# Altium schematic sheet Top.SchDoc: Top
size A4; Date: Not used; ApprovedBy: Not used; CheckedBy: Not used; Author: Not used; CompanyName: STMicroelectronics; DrawnBy: Not used; Engineer: Not used; Organization: Not used; Address1: Not used; Address2: Not used; Address3: Not used; Address4: Not used; DocumentNumber: Not used; Revision: Not used; SheetNumber: 2; SheetTotal: 12
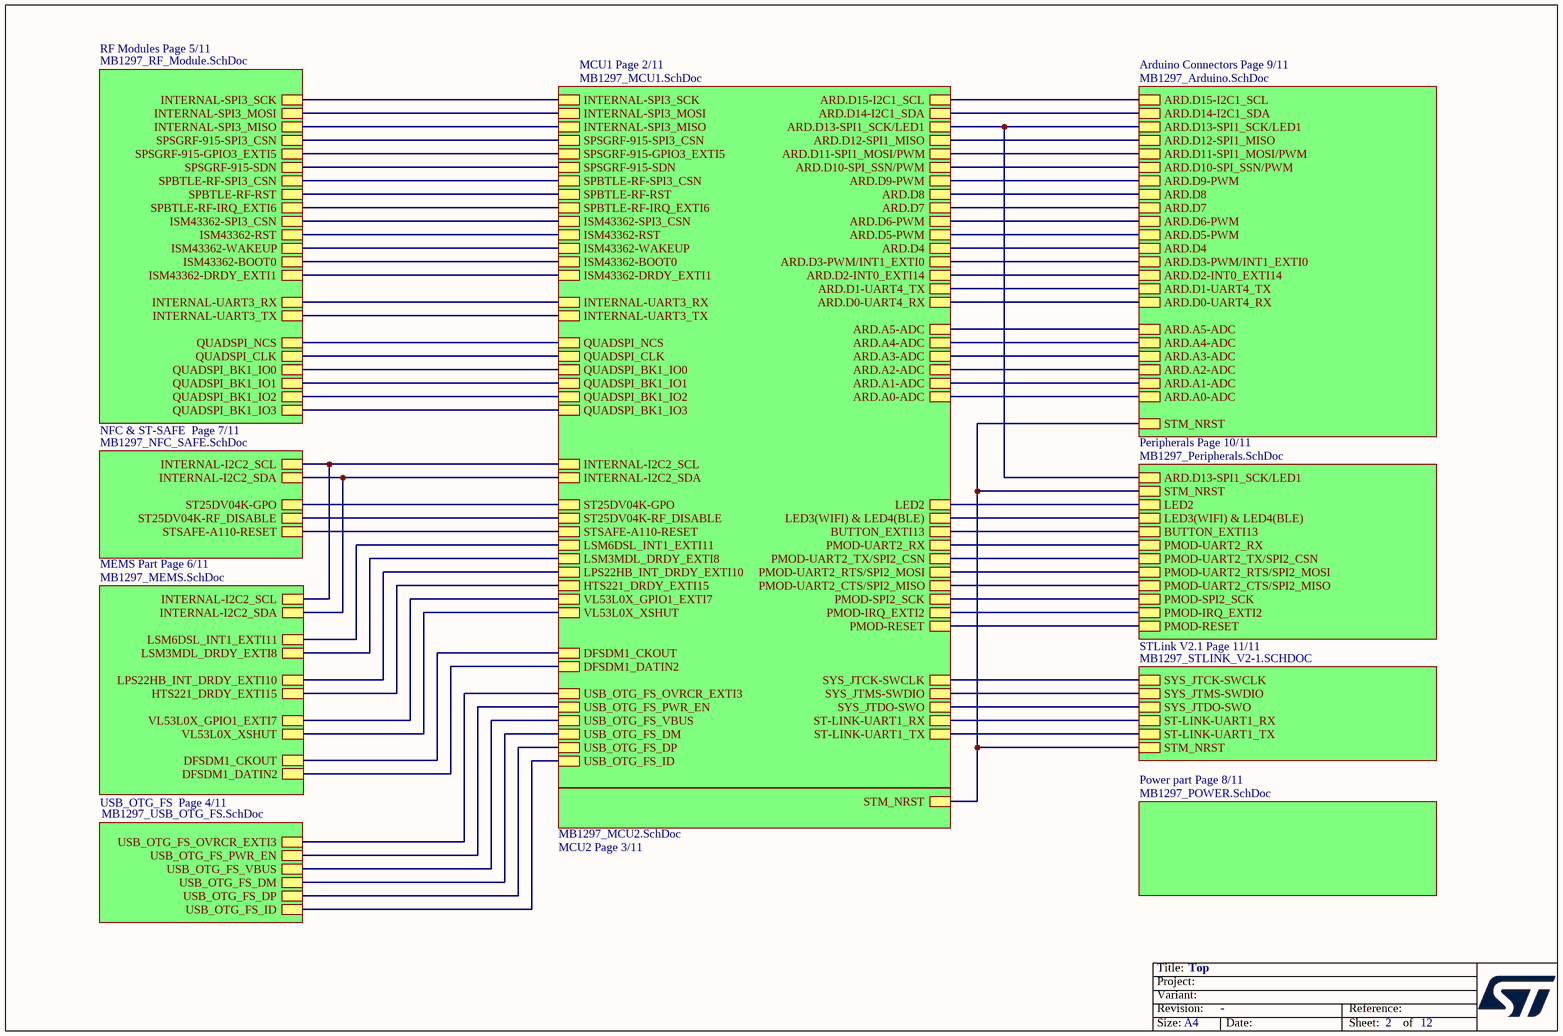
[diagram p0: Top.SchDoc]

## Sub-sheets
Arduino Connectors Page 9/11 = MB1297_Arduino.SchDoc: ARD.D3-PWM/INT1_EXTI0, ARD.D2-INT0_EXTI14, ARD.D1-UART4_TX, ARD.D0-UART4_RX, ARD.A5-ADC, ARD.A4-ADC, ARD.A3-ADC, ARD.A2-ADC, ARD.A1-ADC, ARD.A0-ADC, ARD.D4, ARD.D5-PWM, ARD.D6-PWM, ARD.D7, ARD.D8, ARD.D9-PWM, ARD.D10-SPI_SSN/PWM, ARD.D11-SPI1_MOSI/PWM, ARD.D12-SPI1_MISO, ARD.D13-SPI1_SCK/LED1, ARD.D14-I2C1_SDA, ARD.D15-I2C1_SCL, STM_NRST
MCU1 Page 2/11 = MB1297_MCU1.SchDoc: INTERNAL-SPI3_SCK, INTERNAL-SPI3_MOSI, INTERNAL-SPI3_MISO, ISM43362-SPI3_CSN, SPSGRF-915-SDN, SPSGRF-915-SPI3_CSN, SPBTLE-RF-SPI3_CSN, SYS_JTCK-SWCLK, SYS_JTMS-SWDIO, ARD.D3-PWM/INT1_EXTI0, ARD.D2-INT0_EXTI14, ARD.D1-UART4_TX, ARD.D0-UART4_RX, ARD.D4, ARD.D5-PWM, ARD.D6-PWM, ARD.D7, ARD.D8, ARD.D9-PWM, ARD.D10-SPI_SSN/PWM, ARD.D11-SPI1_MOSI/PWM, ARD.D12-SPI1_MISO, ARD.D13-SPI1_SCK/LED1, ARD.D14-I2C1_SDA, ARD.D15-I2C1_SCL, ARD.A5-ADC, ARD.A4-ADC, ARD.A3-ADC, ARD.A2-ADC, ARD.A1-ADC, ARD.A0-ADC, USB_OTG_FS_OVRCR_EXTI3, USB_OTG_FS_PWR_EN, USB_OTG_FS_VBUS, USB_OTG_FS_DM, USB_OTG_FS_DP, USB_OTG_FS_ID, INTERNAL-I2C2_SCL, INTERNAL-I2C2_SDA, ST25DV04K-GPO, ST25DV04K-RF_DISABLE, STSAFE-A110-RESET, LED2, LED3(WIFI) & LED4(BLE), BUTTON_EXTI13, PMOD-UART2_RTS/SPI2_MOSI, PMOD-UART2_CTS/SPI2_MISO, PMOD-SPI2_SCK, PMOD-IRQ_EXTI2, PMOD-RESET, PMOD-UART2_RX, PMOD-UART2_TX/SPI2_CSN, LSM6DSL_INT1_EXTI11, LSM3MDL_DRDY_EXTI8, LPS22HB_INT_DRDY_EXTI10, HTS221_DRDY_EXTI15, VL53L0X_GPIO1_EXTI7, VL53L0X_XSHUT, DFSDM1_CKOUT, DFSDM1_DATIN2, SPBTLE-RF-RST, SYS_JTDO-SWO, QUADSPI_NCS, QUADSPI_CLK, QUADSPI_BK1_IO0, QUADSPI_BK1_IO1, QUADSPI_BK1_IO2, QUADSPI_BK1_IO3, SPSGRF-915-GPIO3_EXTI5, SPBTLE-RF-IRQ_EXTI6, ISM43362-DRDY_EXTI1, ISM43362-RST, ISM43362-WAKEUP, ISM43362-BOOT0, INTERNAL-UART3_RX, INTERNAL-UART3_TX, ST-LINK-UART1_RX, ST-LINK-UART1_TX
MCU2 Page 3/11 = MB1297_MCU2.SchDoc: STM_NRST
MEMS Part Page 6/11 = MB1297_MEMS.SchDoc: INTERNAL-I2C2_SCL, INTERNAL-I2C2_SDA, LSM6DSL_INT1_EXTI11, LSM3MDL_DRDY_EXTI8, LPS22HB_INT_DRDY_EXTI10, HTS221_DRDY_EXTI15, VL53L0X_GPIO1_EXTI7, VL53L0X_XSHUT, DFSDM1_CKOUT, DFSDM1_DATIN2
NFC & ST-SAFE  Page 7/11 = MB1297_NFC_SAFE.SchDoc: INTERNAL-I2C2_SCL, INTERNAL-I2C2_SDA, ST25DV04K-GPO, ST25DV04K-RF_DISABLE, STSAFE-A110-RESET
Peripherals Page 10/11 = MB1297_Peripherals.SchDoc: STM_NRST, ARD.D13-SPI1_SCK/LED1, LED2, LED3(WIFI) & LED4(BLE), BUTTON_EXTI13, PMOD-UART2_RTS/SPI2_MOSI, PMOD-UART2_CTS/SPI2_MISO, PMOD-SPI2_SCK, PMOD-IRQ_EXTI2, PMOD-RESET, PMOD-UART2_RX, PMOD-UART2_TX/SPI2_CSN
Power part Page 8/11 = MB1297_POWER.SchDoc: no entries
RF Modules Page 5/11 = MB1297_RF_Module.SchDoc: INTERNAL-SPI3_SCK, INTERNAL-SPI3_MOSI, INTERNAL-SPI3_MISO, SPSGRF-915-SPI3_CSN, SPSGRF-915-GPIO3_EXTI5, SPSGRF-915-SDN, SPBTLE-RF-SPI3_CSN, SPBTLE-RF-RST, SPBTLE-RF-IRQ_EXTI6, QUADSPI_NCS, QUADSPI_CLK, QUADSPI_BK1_IO0, QUADSPI_BK1_IO1, QUADSPI_BK1_IO2, QUADSPI_BK1_IO3, INTERNAL-UART3_RX, INTERNAL-UART3_TX, ISM43362-SPI3_CSN, ISM43362-RST, ISM43362-WAKEUP, ISM43362-BOOT0, ISM43362-DRDY_EXTI1
STLink V2.1 Page 11/11 = MB1297_STLINK_V2-1.SCHDOC: SYS_JTCK-SWCLK, SYS_JTMS-SWDIO, SYS_JTDO-SWO, ST-LINK-UART1_RX, ST-LINK-UART1_TX, STM_NRST
USB_OTG_FS  Page 4/11 = MB1297_USB_OTG_FS.SchDoc: USB_OTG_FS_OVRCR_EXTI3, USB_OTG_FS_PWR_EN, USB_OTG_FS_VBUS, USB_OTG_FS_DM, USB_OTG_FS_DP, USB_OTG_FS_ID

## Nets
(unnamed): sheet MCU1 Page 2/11/INTERNAL-SPI3_SCK, sheet RF Modules Page 5/11/INTERNAL-SPI3_SCK
(unnamed): sheet MCU1 Page 2/11/INTERNAL-SPI3_MOSI, sheet RF Modules Page 5/11/INTERNAL-SPI3_MOSI  [a separate net that carries the same name]
(unnamed): sheet MCU1 Page 2/11/INTERNAL-SPI3_MISO, sheet RF Modules Page 5/11/INTERNAL-SPI3_MISO  [a separate net that carries the same name]
(unnamed): sheet MCU1 Page 2/11/ISM43362-SPI3_CSN, sheet RF Modules Page 5/11/ISM43362-SPI3_CSN  [a separate net that carries the same name]
(unnamed): sheet MCU1 Page 2/11/SPSGRF-915-SDN, sheet RF Modules Page 5/11/SPSGRF-915-SDN  [a separate net that carries the same name]
(unnamed): sheet MCU1 Page 2/11/SPSGRF-915-SPI3_CSN, sheet RF Modules Page 5/11/SPSGRF-915-SPI3_CSN  [a separate net that carries the same name]
(unnamed): sheet MCU1 Page 2/11/SPBTLE-RF-SPI3_CSN, sheet RF Modules Page 5/11/SPBTLE-RF-SPI3_CSN  [a separate net that carries the same name]
(unnamed): sheet MCU1 Page 2/11/SYS_JTCK-SWCLK, sheet STLink V2.1 Page 11/11/SYS_JTCK-SWCLK  [a separate net that carries the same name]
(unnamed): sheet MCU1 Page 2/11/SYS_JTMS-SWDIO, sheet STLink V2.1 Page 11/11/SYS_JTMS-SWDIO  [a separate net that carries the same name]
(unnamed): sheet MCU1 Page 2/11/ARD.D3-PWM/INT1_EXTI0, sheet Arduino Connectors Page 9/11/ARD.D3-PWM/INT1_EXTI0  [a separate net that carries the same name]
(unnamed): sheet MCU1 Page 2/11/ARD.D2-INT0_EXTI14, sheet Arduino Connectors Page 9/11/ARD.D2-INT0_EXTI14  [a separate net that carries the same name]
(unnamed): sheet MCU1 Page 2/11/ARD.D1-UART4_TX, sheet Arduino Connectors Page 9/11/ARD.D1-UART4_TX  [a separate net that carries the same name]
(unnamed): sheet MCU1 Page 2/11/ARD.D0-UART4_RX, sheet Arduino Connectors Page 9/11/ARD.D0-UART4_RX  [a separate net that carries the same name]
(unnamed): sheet MCU1 Page 2/11/ARD.D4, sheet Arduino Connectors Page 9/11/ARD.D4  [a separate net that carries the same name]
(unnamed): sheet MCU1 Page 2/11/ARD.D5-PWM, sheet Arduino Connectors Page 9/11/ARD.D5-PWM  [a separate net that carries the same name]
(unnamed): sheet MCU1 Page 2/11/ARD.D6-PWM, sheet Arduino Connectors Page 9/11/ARD.D6-PWM  [a separate net that carries the same name]
(unnamed): sheet MCU1 Page 2/11/ARD.D7, sheet Arduino Connectors Page 9/11/ARD.D7  [a separate net that carries the same name]
(unnamed): sheet MCU1 Page 2/11/ARD.D8, sheet Arduino Connectors Page 9/11/ARD.D8  [a separate net that carries the same name]
(unnamed): sheet MCU1 Page 2/11/ARD.D9-PWM, sheet Arduino Connectors Page 9/11/ARD.D9-PWM  [a separate net that carries the same name]
(unnamed): sheet MCU1 Page 2/11/ARD.D10-SPI_SSN/PWM, sheet Arduino Connectors Page 9/11/ARD.D10-SPI_SSN/PWM  [a separate net that carries the same name]
(unnamed): sheet MCU1 Page 2/11/ARD.D11-SPI1_MOSI/PWM, sheet Arduino Connectors Page 9/11/ARD.D11-SPI1_MOSI/PWM  [a separate net that carries the same name]
(unnamed): sheet MCU1 Page 2/11/ARD.D12-SPI1_MISO, sheet Arduino Connectors Page 9/11/ARD.D12-SPI1_MISO  [a separate net that carries the same name]
(unnamed): sheet MCU1 Page 2/11/ARD.D13-SPI1_SCK/LED1, sheet Peripherals Page 10/11/ARD.D13-SPI1_SCK/LED1, sheet Arduino Connectors Page 9/11/ARD.D13-SPI1_SCK/LED1  [a separate net that carries the same name]
(unnamed): sheet MCU1 Page 2/11/ARD.D14-I2C1_SDA, sheet Arduino Connectors Page 9/11/ARD.D14-I2C1_SDA  [a separate net that carries the same name]
(unnamed): sheet MCU1 Page 2/11/ARD.D15-I2C1_SCL, sheet Arduino Connectors Page 9/11/ARD.D15-I2C1_SCL  [a separate net that carries the same name]
(unnamed): sheet MCU1 Page 2/11/ARD.A5-ADC, sheet Arduino Connectors Page 9/11/ARD.A5-ADC  [a separate net that carries the same name]
(unnamed): sheet MCU1 Page 2/11/ARD.A4-ADC, sheet Arduino Connectors Page 9/11/ARD.A4-ADC  [a separate net that carries the same name]
(unnamed): sheet MCU1 Page 2/11/ARD.A3-ADC, sheet Arduino Connectors Page 9/11/ARD.A3-ADC  [a separate net that carries the same name]
(unnamed): sheet MCU1 Page 2/11/ARD.A2-ADC, sheet Arduino Connectors Page 9/11/ARD.A2-ADC  [a separate net that carries the same name]
(unnamed): sheet MCU1 Page 2/11/ARD.A1-ADC, sheet Arduino Connectors Page 9/11/ARD.A1-ADC  [a separate net that carries the same name]
(unnamed): sheet MCU1 Page 2/11/ARD.A0-ADC, sheet Arduino Connectors Page 9/11/ARD.A0-ADC  [a separate net that carries the same name]
(unnamed): sheet MCU1 Page 2/11/USB_OTG_FS_OVRCR_EXTI3, sheet USB_OTG_FS  Page 4/11/USB_OTG_FS_OVRCR_EXTI3  [a separate net that carries the same name]
(unnamed): sheet MCU1 Page 2/11/USB_OTG_FS_PWR_EN, sheet USB_OTG_FS  Page 4/11/USB_OTG_FS_PWR_EN  [a separate net that carries the same name]
(unnamed): sheet MCU1 Page 2/11/USB_OTG_FS_VBUS, sheet USB_OTG_FS  Page 4/11/USB_OTG_FS_VBUS  [a separate net that carries the same name]
(unnamed): sheet MCU1 Page 2/11/USB_OTG_FS_DM, sheet USB_OTG_FS  Page 4/11/USB_OTG_FS_DM  [a separate net that carries the same name]
(unnamed): sheet MCU1 Page 2/11/USB_OTG_FS_DP, sheet USB_OTG_FS  Page 4/11/USB_OTG_FS_DP  [a separate net that carries the same name]
(unnamed): sheet MCU1 Page 2/11/USB_OTG_FS_ID, sheet USB_OTG_FS  Page 4/11/USB_OTG_FS_ID  [a separate net that carries the same name]
(unnamed): sheet MCU1 Page 2/11/INTERNAL-I2C2_SCL, sheet NFC & ST-SAFE  Page 7/11/INTERNAL-I2C2_SCL, sheet MEMS Part Page 6/11/INTERNAL-I2C2_SCL  [a separate net that carries the same name]
(unnamed): sheet MCU1 Page 2/11/INTERNAL-I2C2_SDA, sheet NFC & ST-SAFE  Page 7/11/INTERNAL-I2C2_SDA, sheet MEMS Part Page 6/11/INTERNAL-I2C2_SDA  [a separate net that carries the same name]
(unnamed): sheet MCU1 Page 2/11/ST25DV04K-GPO, sheet NFC & ST-SAFE  Page 7/11/ST25DV04K-GPO  [a separate net that carries the same name]
(unnamed): sheet MCU1 Page 2/11/ST25DV04K-RF_DISABLE, sheet NFC & ST-SAFE  Page 7/11/ST25DV04K-RF_DISABLE  [a separate net that carries the same name]
(unnamed): sheet MCU1 Page 2/11/STSAFE-A110-RESET, sheet NFC & ST-SAFE  Page 7/11/STSAFE-A110-RESET  [a separate net that carries the same name]
(unnamed): sheet MCU1 Page 2/11/LED2, sheet Peripherals Page 10/11/LED2  [a separate net that carries the same name]
(unnamed): sheet MCU1 Page 2/11/LED3(WIFI) & LED4(BLE), sheet Peripherals Page 10/11/LED3(WIFI) & LED4(BLE)  [a separate net that carries the same name]
(unnamed): sheet MCU1 Page 2/11/BUTTON_EXTI13, sheet Peripherals Page 10/11/BUTTON_EXTI13  [a separate net that carries the same name]
(unnamed): sheet MCU1 Page 2/11/PMOD-UART2_RTS/SPI2_MOSI, sheet Peripherals Page 10/11/PMOD-UART2_RTS/SPI2_MOSI  [a separate net that carries the same name]
(unnamed): sheet MCU1 Page 2/11/PMOD-UART2_CTS/SPI2_MISO, sheet Peripherals Page 10/11/PMOD-UART2_CTS/SPI2_MISO  [a separate net that carries the same name]
(unnamed): sheet MCU1 Page 2/11/PMOD-SPI2_SCK, sheet Peripherals Page 10/11/PMOD-SPI2_SCK  [a separate net that carries the same name]
(unnamed): sheet MCU1 Page 2/11/PMOD-IRQ_EXTI2, sheet Peripherals Page 10/11/PMOD-IRQ_EXTI2  [a separate net that carries the same name]
(unnamed): sheet MCU1 Page 2/11/PMOD-RESET, sheet Peripherals Page 10/11/PMOD-RESET  [a separate net that carries the same name]
(unnamed): sheet MCU1 Page 2/11/PMOD-UART2_RX, sheet Peripherals Page 10/11/PMOD-UART2_RX  [a separate net that carries the same name]
(unnamed): sheet MCU1 Page 2/11/PMOD-UART2_TX/SPI2_CSN, sheet Peripherals Page 10/11/PMOD-UART2_TX/SPI2_CSN  [a separate net that carries the same name]
(unnamed): sheet MCU1 Page 2/11/LSM6DSL_INT1_EXTI11, sheet MEMS Part Page 6/11/LSM6DSL_INT1_EXTI11  [a separate net that carries the same name]
(unnamed): sheet MCU1 Page 2/11/LSM3MDL_DRDY_EXTI8, sheet MEMS Part Page 6/11/LSM3MDL_DRDY_EXTI8  [a separate net that carries the same name]
(unnamed): sheet MCU1 Page 2/11/LPS22HB_INT_DRDY_EXTI10, sheet MEMS Part Page 6/11/LPS22HB_INT_DRDY_EXTI10  [a separate net that carries the same name]
(unnamed): sheet MCU1 Page 2/11/HTS221_DRDY_EXTI15, sheet MEMS Part Page 6/11/HTS221_DRDY_EXTI15  [a separate net that carries the same name]
(unnamed): sheet MCU1 Page 2/11/VL53L0X_GPIO1_EXTI7, sheet MEMS Part Page 6/11/VL53L0X_GPIO1_EXTI7  [a separate net that carries the same name]
(unnamed): sheet MCU1 Page 2/11/VL53L0X_XSHUT, sheet MEMS Part Page 6/11/VL53L0X_XSHUT  [a separate net that carries the same name]
(unnamed): sheet MCU1 Page 2/11/DFSDM1_CKOUT, sheet MEMS Part Page 6/11/DFSDM1_CKOUT  [a separate net that carries the same name]
(unnamed): sheet MCU1 Page 2/11/DFSDM1_DATIN2, sheet MEMS Part Page 6/11/DFSDM1_DATIN2  [a separate net that carries the same name]
(unnamed): sheet MCU1 Page 2/11/SPBTLE-RF-RST, sheet RF Modules Page 5/11/SPBTLE-RF-RST  [a separate net that carries the same name]
(unnamed): sheet MCU1 Page 2/11/SYS_JTDO-SWO, sheet STLink V2.1 Page 11/11/SYS_JTDO-SWO  [a separate net that carries the same name]
(unnamed): sheet MCU1 Page 2/11/QUADSPI_NCS, sheet RF Modules Page 5/11/QUADSPI_NCS  [a separate net that carries the same name]
(unnamed): sheet MCU1 Page 2/11/QUADSPI_CLK, sheet RF Modules Page 5/11/QUADSPI_CLK  [a separate net that carries the same name]
(unnamed): sheet MCU1 Page 2/11/QUADSPI_BK1_IO0, sheet RF Modules Page 5/11/QUADSPI_BK1_IO0  [a separate net that carries the same name]
(unnamed): sheet MCU1 Page 2/11/QUADSPI_BK1_IO1, sheet RF Modules Page 5/11/QUADSPI_BK1_IO1  [a separate net that carries the same name]
(unnamed): sheet MCU1 Page 2/11/QUADSPI_BK1_IO2, sheet RF Modules Page 5/11/QUADSPI_BK1_IO2  [a separate net that carries the same name]
(unnamed): sheet MCU1 Page 2/11/QUADSPI_BK1_IO3, sheet RF Modules Page 5/11/QUADSPI_BK1_IO3  [a separate net that carries the same name]
(unnamed): sheet MCU1 Page 2/11/SPSGRF-915-GPIO3_EXTI5, sheet RF Modules Page 5/11/SPSGRF-915-GPIO3_EXTI5  [a separate net that carries the same name]
(unnamed): sheet MCU1 Page 2/11/SPBTLE-RF-IRQ_EXTI6, sheet RF Modules Page 5/11/SPBTLE-RF-IRQ_EXTI6  [a separate net that carries the same name]
(unnamed): sheet MCU1 Page 2/11/ISM43362-DRDY_EXTI1, sheet RF Modules Page 5/11/ISM43362-DRDY_EXTI1  [a separate net that carries the same name]
(unnamed): sheet MCU1 Page 2/11/ISM43362-RST, sheet RF Modules Page 5/11/ISM43362-RST  [a separate net that carries the same name]
(unnamed): sheet MCU1 Page 2/11/ISM43362-WAKEUP, sheet RF Modules Page 5/11/ISM43362-WAKEUP  [a separate net that carries the same name]
(unnamed): sheet MCU1 Page 2/11/ISM43362-BOOT0, sheet RF Modules Page 5/11/ISM43362-BOOT0  [a separate net that carries the same name]
(unnamed): sheet MCU1 Page 2/11/INTERNAL-UART3_RX, sheet RF Modules Page 5/11/INTERNAL-UART3_RX  [a separate net that carries the same name]
(unnamed): sheet MCU1 Page 2/11/INTERNAL-UART3_TX, sheet RF Modules Page 5/11/INTERNAL-UART3_TX  [a separate net that carries the same name]
(unnamed): sheet MCU1 Page 2/11/ST-LINK-UART1_RX, sheet STLink V2.1 Page 11/11/ST-LINK-UART1_RX  [a separate net that carries the same name]
(unnamed): sheet MCU1 Page 2/11/ST-LINK-UART1_TX, sheet STLink V2.1 Page 11/11/ST-LINK-UART1_TX  [a separate net that carries the same name]
(unnamed): sheet MCU2 Page 3/11/STM_NRST, sheet Peripherals Page 10/11/STM_NRST, sheet STLink V2.1 Page 11/11/STM_NRST, sheet Arduino Connectors Page 9/11/STM_NRST  [a separate net that carries the same name]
